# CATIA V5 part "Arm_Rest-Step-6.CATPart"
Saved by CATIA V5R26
Part number: Arm_Rest
Bounding box of the stored display mesh (mm): x 743.798 to 1432.298, y -782.976 to -630.25, z 345.981 to 534.311
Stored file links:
  D:\LinkedIn Learning\NURBS\CATIA\Class Parts\Arm_Rest-Step-7.CATPart
  D:\LinkedIn Learning\NURBS\Arm_Rest.CATPart
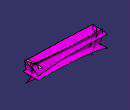
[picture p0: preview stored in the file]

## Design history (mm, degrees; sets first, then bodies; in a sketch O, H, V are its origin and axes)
AxisSystem1: origin (0, 0, 0), X (1, 0, 0), Y (0, 1, 0), Z (0, 0, 1)
StDynAnalysisRootNodeFeature1 "CATStDynAnalysisRootNodeName"
Set1 "REF DATA"
  CLDGeom1 "TOP"
  CLDGeom2 "FRONT"
  CLDGeom3 "AFT_BLEND"
  CLDGeom4 "END_AFT"
  CLDGeom5 "FORWARD_BLEND"
  CLDGeom6 "BOTTOM"
  CLDGeom7 "END_FORWARD"
  CLDGeom8 "UPPER_BLENDS"
  CLDGeom9 "LOWER_BLENDS"
  DatumSurface1 "DOOR_TRIM_SURFACE"
Set2 "FORM"
  Set3 "SLABS"
    DatumSurface2 to DatumSurface6
  Set4 "CURVES"
    St3DCurveFeature1 "CATSt3DCurveFeatureName": Order 6, CreationType 1, ClosureMode false, ConstructionPoints ({point type Coord, X 863.1168, Y 0, Z 551.1449}; {point type Coord, X 868.9503, Y 0, Z 330.43}), SymmetryMode false
    St3DCurveFeature2 "CATSt3DCurveFeatureName": Order 6, CreationType 1, ClosureMode false, ConstructionPoints ({point type Coord, X 1369.3867, Y 0, Z 551.9965}; {point type Coord, X 1358.4038, Y 0, Z 335.6826}), SymmetryMode false
    Intersect1: ToIntersect1 DatumSurface4, ToIntersect2 DatumSurface5
    Intersect2: ToIntersect1 DatumSurface6, ToIntersect2 DatumSurface4
    CurvePar1: Offset Intersect2, Support DatumSurface6, Offset2 0, Offset1 30
    CurvePar2: Offset Intersect1, Support DatumSurface5, Offset2 50, Offset1 20
    Project1: ToProject St3DCurveFeature1, Support DatumSurface4, Direction edge [YZ plane of AxisSystem1 | XY plane of AxisSystem1]
    Project2: ToProject St3DCurveFeature2, Support DatumSurface4, Direction edge [YZ plane of AxisSystem1 | XY plane of AxisSystem1]
  Set5 "BLENDS"
    Blend1: StartLimit {blendlimit Curve Project1, Support DatumSurface4, TensionValues 1.1}, EndLimit {blendlimit Curve CurvePar2, Support DatumSurface5, TensionValues 1}
    Blend2: StartLimit {blendlimit Curve CurvePar1, Support DatumSurface6, TensionValues 0.9}, EndLimit {blendlimit Curve Project2, Support DatumSurface4, TensionValues 0.8}
    StTopoTypeFeature1 "CATStTopoTypeFeatureName": Children 15
    StTopoTypeFeature2 "CATStTopoTypeFeatureName": Children 35
    StTopoTypeFeature3 "CATStTopoTypeFeatureName": nls://CATStFeaturesStartUpsNLS/TopoVarRadiCke 35, nls://CATStFeaturesStartUpsNLS/TopoVarRadiCke 15
Body1 (main body)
